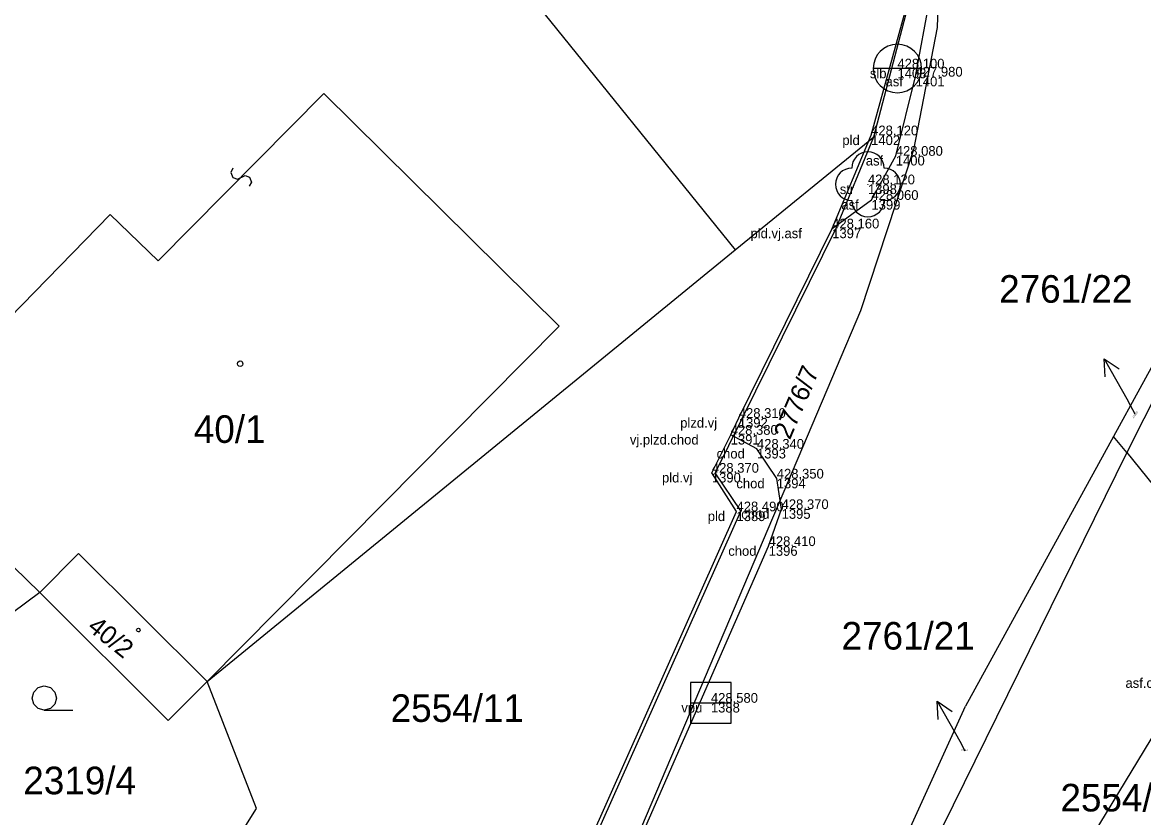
# Model space of a CAD drawing. Extents: x -747792 to -745414, y -1093712 to -1091463.
# Drawn here: x -746629.9 to -746595.34, y -1092941.98 to -1092917.47 of the extents above; entities that cross this region are included whole.
import ezdxf

# ---------------------------------------------------------------- set-up
doc = ezdxf.new("R2010")
doc.units = 0
for name, color, linetype in [('Budovy', 7, 'Continuous'), ('Doplňkové značky', 7, 'Continuous'), ('Hladina', 7, 'Continuous'), ('Koleje_dopravní prvky', 7, 'Continuous'), ('Kultury', 7, 'Continuous'), ('Nezařazené objekty', 7, 'Continuous'), ('Nivelační značky_hrany', 7, 'Continuous'), ('Ploty_opěrné zdi', 7, 'Continuous'), ('Pracovní_bod JDTM STC_VC - výška', 7, 'Continuous'), ('Pracovní_bod PPBP - výška', 7, 'Continuous'), ('Rozhraní ploch', 7, 'Continuous'), ('Stromy_porost', 7, 'Continuous'), ('Výškopis', 7, 'Continuous'), ('Čísla popisná_parcelní', 7, 'Continuous')]:
    doc.layers.add(name, color=color, linetype=linetype)

msp = doc.modelspace()

# ---------------------------------------------------------------- linework, layer by layer
at = {"layer": 'Budovy'}
msp.add_lwpolyline([(-746629.23, -1092938.67), (-746629.42, -1092938.62), (-746629.555, -1092938.48), (-746629.605, -1092938.295), (-746629.555, -1092938.11), (-746629.42, -1092937.97), (-746629.23, -1092937.92), (-746629.04, -1092937.97), (-746628.905, -1092938.11), (-746628.855, -1092938.295), (-746628.905, -1092938.48), (-746629.04, -1092938.62), (-746629.23, -1092938.67), (-746628.355, -1092938.67)], dxfattribs=at)
at = {"layer": 'Doplňkové značky'}
for points in [[(-746596.558, -1092927.834), (-746595.82, -1092929.14)], [(-746596.529, -1092928.392), (-746596.558, -1092927.834), (-746596.094, -1092928.146)], [(-746595.6, -1092929.54), (-746595.82, -1092929.14)], [(-746601.706, -1092938.393), (-746600.97, -1092939.7)], [(-746601.679, -1092938.951), (-746601.706, -1092938.393), (-746601.243, -1092938.706)], [(-746600.84, -1092939.93), (-746600.97, -1092939.7)]]:
    msp.add_lwpolyline(points, dxfattribs=at)
at = {"layer": 'Hladina'}
for p, q in [((-746602.93, -1092918.89), (-746602.93, -1092918.89)), ((-746602.37, -1092919.14), (-746602.37, -1092919.14)), ((-746603.74, -1092920.95), (-746603.74, -1092920.95)), ((-746602.98, -1092921.58), (-746602.98, -1092921.58)), ((-746603.84, -1092922.46), (-746603.84, -1092922.46)), ((-746603.73, -1092922.94), (-746603.73, -1092922.94)), ((-746604.94, -1092923.82), (-746604.94, -1092923.82)), ((-746607.82, -1092929.66), (-746607.82, -1092929.66)), ((-746608.07, -1092930.18), (-746608.07, -1092930.18)), ((-746607.26, -1092930.61), (-746607.26, -1092930.61)), ((-746608.65, -1092931.35), (-746608.65, -1092931.35)), ((-746606.65, -1092931.53), (-746606.65, -1092931.53)), ((-746607.89, -1092932.54), (-746607.89, -1092932.54)), ((-746606.5, -1092932.47), (-746606.5, -1092932.47)), ((-746606.9, -1092933.61), (-746606.9, -1092933.61)), ((-746608.68, -1092938.44), (-746608.68, -1092938.44))]:
    msp.add_line(p, q, dxfattribs=at)
at = {"layer": 'Kultury'}
for points in [[(-746625.72, -1092924.82), (-746620.61, -1092919.66)], [(-746620.61, -1092919.66), (-746613.36, -1092926.83)], [(-746623.414, -1092921.958), (-746623.484, -1092922.1), (-746623.416, -1092922.252), (-746623.271, -1092922.297), (-746623.042, -1092922.186), (-746622.9, -1092922.242), (-746622.846, -1092922.394), (-746622.916, -1092922.522)], [(-746631.86, -1092928.17), (-746627.2, -1092923.39)], [(-746627.2, -1092923.39), (-746625.72, -1092924.82)], [(-746613.36, -1092926.83), (-746624.21, -1092937.78)], [(-746629.37, -1092935.04), (-746632.64, -1092931.87)]]:
    msp.add_lwpolyline(points, dxfattribs=at)
at = {"layer": 'Nezařazené objekty'}
for points in [[(-746604.94, -1092923.82), (-746603.74, -1092920.95), (-746602.4, -1092916.09), (-746602.36, -1092913.51), (-746602.45, -1092911.31), (-746604.18, -1092900.66), (-746605.5, -1092896.5)], [(-746608.07, -1092930.18), (-746607.82, -1092929.66)], [(-746629.61, -1092943.93), (-746625.76, -1092946.8), (-746617.81, -1092950.11), (-746615.8, -1092950.31), (-746607.89, -1092932.54), (-746608.65, -1092931.35)]]:
    msp.add_lwpolyline(points, dxfattribs=at)
at = {"layer": 'Nivelační značky_hrany'}
for points in [[(-746604.94, -1092923.82), (-746603.73, -1092922.94), (-746602.98, -1092921.58), (-746602.37, -1092919.14), (-746601.93, -1092916.74), (-746601.75, -1092914.6), (-746601.83, -1092911.07), (-746602.53, -1092905.39), (-746603.47, -1092900.25), (-746604.79, -1092895.49), (-746611.22, -1092875.29), (-746616.25, -1092860.06), (-746619.38, -1092851.1), (-746621.94, -1092852.14)], [(-746567.47, -1092928.76), (-746566.95, -1092927.82), (-746569.47, -1092926.26), (-746577.49, -1092922.09), (-746580.71, -1092921), (-746582.05, -1092920.75), (-746583.67, -1092921.02), (-746585.64, -1092922.33), (-746587.16, -1092923.77), (-746589.64, -1092927.2), (-746592.28, -1092931.27), (-746593.72, -1092934.95), (-746594.32, -1092936.39), (-746593.98, -1092937.68), (-746596.88, -1092942.46), (-746597.95, -1092943.58)], [(-746615.8, -1092950.31), (-746614.56, -1092950.23), (-746614.12, -1092950), (-746613.7, -1092949.12), (-746606.9, -1092933.61), (-746606.5, -1092932.47), (-746606.65, -1092931.53), (-746607.26, -1092930.61), (-746608.07, -1092930.18)]]:
    msp.add_lwpolyline(points, dxfattribs=at)
at = {"layer": 'Ploty_opěrné zdi'}
for points in [[(-746623.19, -1092927.905), (-746623.14, -1092927.915), (-746623.115, -1092927.96), (-746623.105, -1092927.99), (-746623.115, -1092928.035), (-746623.155, -1092928.07), (-746623.19, -1092928.075), (-746623.235, -1092928.06), (-746623.265, -1092928.03), (-746623.275, -1092927.99), (-746623.265, -1092927.945), (-746623.225, -1092927.91)], [(-746626.33, -1092936.143), (-746626.296, -1092936.15), (-746626.28, -1092936.18), (-746626.273, -1092936.2), (-746626.28, -1092936.23), (-746626.307, -1092936.254), (-746626.33, -1092936.257), (-746626.36, -1092936.247), (-746626.38, -1092936.227), (-746626.387, -1092936.2), (-746626.38, -1092936.17), (-746626.353, -1092936.146)]]:
    msp.add_lwpolyline(points, close=True, dxfattribs=at)
at = {"layer": 'Pracovní_bod JDTM STC_VC - výška'}
msp.add_circle((-746603.84, -1092922.46), 0.0005, dxfattribs=at)
for centre, start, end in [((-746603.84, -1092921.96), 0, 180), ((-746604.34, -1092922.46), 90, 270), ((-746603.34, -1092922.46), 270, 90), ((-746603.84, -1092922.96), 180, 360)]:
    msp.add_arc(centre, 0.5, start, end, dxfattribs=at)
at = {"layer": 'Pracovní_bod PPBP - výška'}
for points in [[(-746607.82, -1092929.66), (-746604.94, -1092923.82)], [(-746608.65, -1092931.35), (-746608.07, -1092930.18)]]:
    msp.add_lwpolyline(points, dxfattribs=at)
at = {"layer": 'Stromy_porost'}
for points in [[(-746601.52, -1092911.78), (-746601.7, -1092917.63)], [(-746602.35, -1092915.98), (-746603.67, -1092921.01)], [(-746614.4, -1092916.48), (-746607.93, -1092924.48)], [(-746601.7, -1092917.63), (-746602.43, -1092921.4)], [(-746607.93, -1092924.48), (-746603.67, -1092921.01)], [(-746603.67, -1092921.01), (-746604.83, -1092923.82)], [(-746602.43, -1092921.4), (-746604.07, -1092926.36)], [(-746604.83, -1092923.82), (-746608.55, -1092931.35)], [(-746624.21, -1092937.78), (-746607.93, -1092924.48)], [(-746604.07, -1092926.36), (-746616.96, -1092956.74)], [(-746594.65, -1092927.27), (-746596.27, -1092930.23)], [(-746594.81, -1092928.65), (-746595.86, -1092930.73)], [(-746596.27, -1092930.23), (-746600.83, -1092938.54)], [(-746595.86, -1092930.73), (-746596.27, -1092930.23)], [(-746595.86, -1092930.73), (-746603.22, -1092945.67)], [(-746595.86, -1092930.73), (-746589.37, -1092938.75)], [(-746607.76, -1092932.52), (-746608.55, -1092931.35)], [(-746607.76, -1092932.52), (-746615.71, -1092950.34)], [(-746628.18, -1092933.84), (-746629.37, -1092935.04)], [(-746628.18, -1092933.84), (-746624.21, -1092937.78)], [(-746629.37, -1092935.04), (-746634.6, -1092938.92)], [(-746625.41, -1092938.99), (-746629.37, -1092935.04)], [(-746624.21, -1092937.78), (-746625.41, -1092938.99)], [(-746622.69, -1092941.7), (-746624.21, -1092937.78)], [(-746603.91, -1092945.33), (-746600.83, -1092938.54)], [(-746625.82, -1092946.7), (-746622.69, -1092941.7)]]:
    msp.add_lwpolyline(points, dxfattribs=at)
at = {"layer": 'Čísla popisná_parcelní'}
for p, q in [((-746602.182, -1092918.89), (-746603.677, -1092918.89)), ((-746608.054, -1092937.813), (-746609.306, -1092937.813)), ((-746609.306, -1092937.813), (-746609.306, -1092939.067)), ((-746608.054, -1092939.067), (-746608.054, -1092937.813)), ((-746609.306, -1092938.44), (-746608.056, -1092938.44)), ((-746609.306, -1092939.067), (-746608.054, -1092939.067))]:
    msp.add_line(p, q, dxfattribs=at)
for start, end in [(0, 180), (180, 0)]:
    msp.add_arc((-746602.93, -1092918.89), 0.747, start, end, dxfattribs=at)

# ---------------------------------------------------------------- texts
at = {"layer": 'Doplňkové značky'}
for s, p in [('2761/22', (-746599.794, -1092926.11)), ('2761/21', (-746604.653, -1092936.8))]:
    msp.add_text(s, height=0.85, dxfattribs=at).set_placement(p)
at = {"layer": 'Koleje_dopravní prvky'}
for s, height, rotation, p in [('2776/7', 0.57, 66.9788, (-746606.244, -1092930.358)), ('2761/22', 0.05, 56.3218, (-746595.646, -1092929.674)), ('40/2', 0.57, 321.1428, (-746627.933, -1092936.172))]:
    msp.add_text(s, height=height, rotation=rotation, dxfattribs=at).set_placement(p)
for s, height, p in [('40/1', 0.85, (-746624.621, -1092930.43)), ('2554/11', 0.85, (-746618.552, -1092939.03)), ('2761/21', 0.05, (-746600.964, -1092939.93)), ('2319/4', 0.85, (-746629.878, -1092941.26)), ('2554/7', 0.85, (-746597.905, -1092941.79))]:
    msp.add_text(s, height=height, dxfattribs=at).set_placement(p)
at = {"layer": 'Rozhraní ploch'}
for s, p in [(' slb', (-746603.891, -1092919.19)), ('1403', (-746602.93, -1092919.19)), (' asf', (-746603.407, -1092919.44)), ('1401', (-746602.37, -1092919.44)), (' pld', (-746604.739, -1092921.25)), ('1402', (-746603.74, -1092921.25)), (' asf', (-746604.017, -1092921.88)), ('1400', (-746602.98, -1092921.88)), (' str', (-746604.818, -1092922.76)), ('1398', (-746603.84, -1092922.76)), (' asf', (-746604.767, -1092923.24)), ('1399', (-746603.73, -1092923.24)), (' pld.vj.asf', (-746607.571, -1092924.12)), ('1397', (-746604.94, -1092924.12)), (' plzd.vj', (-746609.738, -1092929.96)), ('1392', (-746607.82, -1092929.96)), (' vj.plzd.chod', (-746611.289, -1092930.48)), ('1391', (-746608.07, -1092930.48)), (' chod', (-746608.616, -1092930.91)), ('1393', (-746607.26, -1092930.91)), (' pld.vj', (-746610.299, -1092931.65)), ('1390', (-746608.65, -1092931.65)), (' chod', (-746608.006, -1092931.83)), ('1394', (-746606.65, -1092931.83)), (' pld', (-746608.889, -1092932.84)), ('1389', (-746607.89, -1092932.84)), (' chod', (-746607.856, -1092932.77)), ('1395', (-746606.5, -1092932.77)), (' chod', (-746608.256, -1092933.91)), ('1396', (-746606.9, -1092933.91)), (' asf.ces', (-746596.011, -1092937.98)), (' vpu', (-746609.703, -1092938.74)), ('1388', (-746608.68, -1092938.74))]:
    msp.add_text(s, height=0.3, dxfattribs=at).set_placement(p)
at = {"layer": 'Výškopis'}
for s, p in [('428,100', (-746602.93, -1092918.89)), ('427,980', (-746602.37, -1092919.14)), ('428,120', (-746603.74, -1092920.95)), ('428,080', (-746602.98, -1092921.58)), ('428,120', (-746603.84, -1092922.46)), ('428,060', (-746603.73, -1092922.94)), ('428,160', (-746604.94, -1092923.82)), ('428,310', (-746607.82, -1092929.66)), ('428,380', (-746608.07, -1092930.18)), ('428,340', (-746607.26, -1092930.61)), ('428,370', (-746608.65, -1092931.35)), ('428,350', (-746606.65, -1092931.53)), ('428,370', (-746606.5, -1092932.47)), ('428,490', (-746607.89, -1092932.54)), ('428,410', (-746606.9, -1092933.61)), ('428,580', (-746608.68, -1092938.44))]:
    msp.add_text(s, height=0.3, dxfattribs=at).set_placement(p)

doc.saveas('drawing.dxf')
